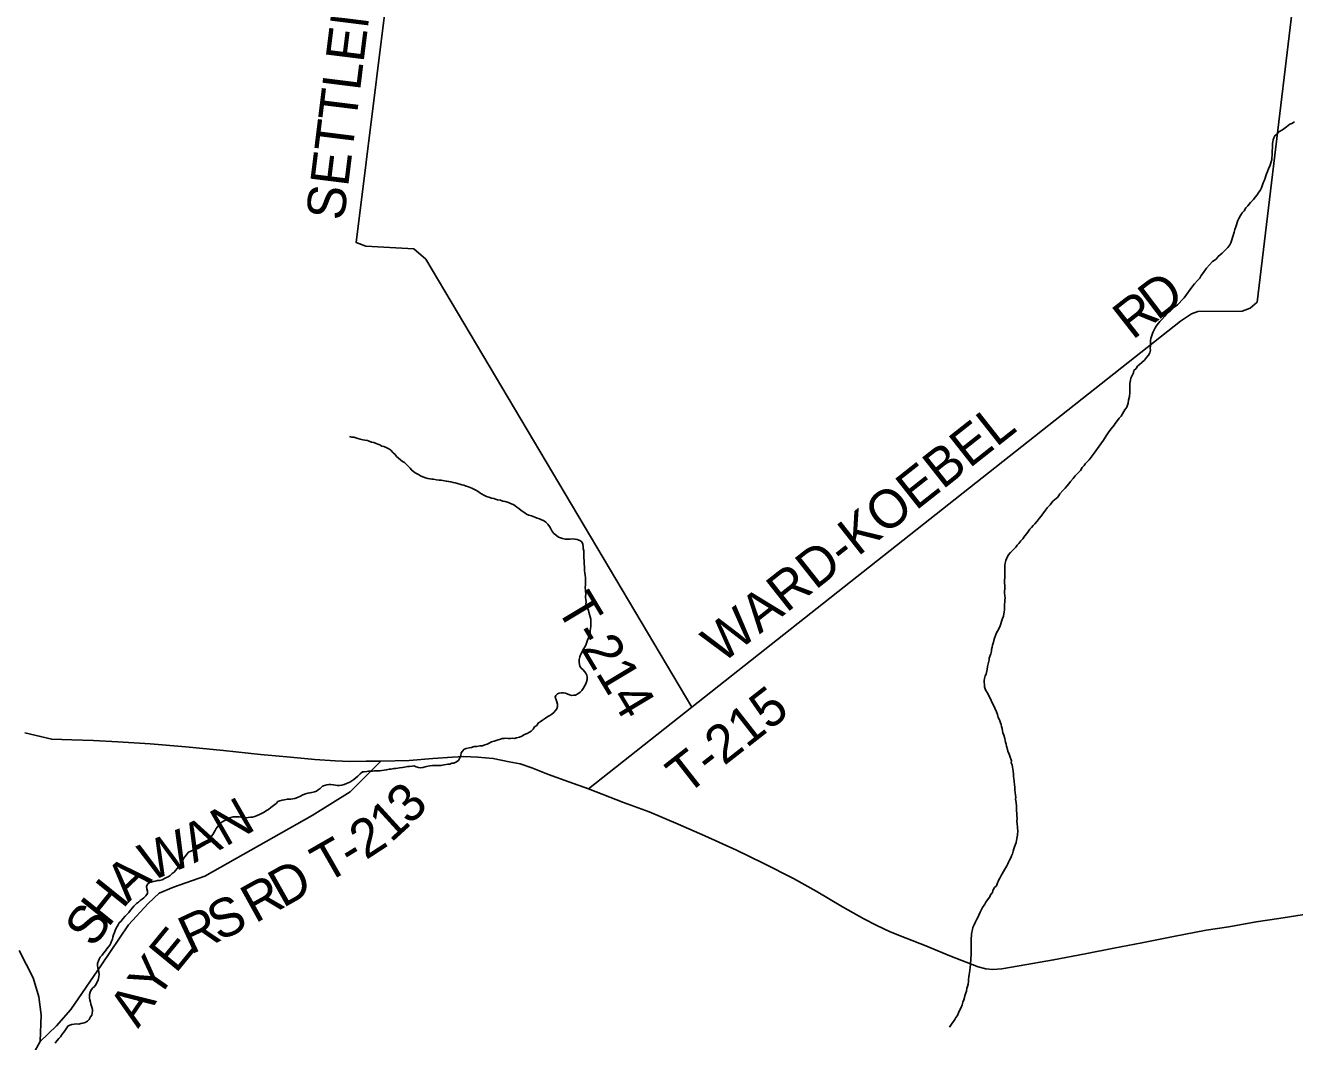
# Model space of a CAD drawing. Extents: x 0.4 to 34.4, y -2.1 to 19.9.
# Drawn here: x 5.213 to 7.097, y 12.684 to 14.193 of the extents above; entities that cross this region are included whole.
import ezdxf

# ---------------------------------------------------------------- set-up
doc = ezdxf.new("R2010")
doc.units = 0
for name, color, linetype in [('GM_X_County_Road', 7, 'Continuous'), ('GM_X_Minor_River', 7, 'Continuous'), ('GM_X_State_Route', 7, 'Continuous'), ('GM_X_Township_Road', 7, 'Continuous'), ('GM_X_Township_Road_Text', 7, 'Continuous')]:
    doc.layers.add(name, color=color, linetype=linetype)

msp = doc.modelspace()

# ---------------------------------------------------------------- linework, layer by layer
at = {"layer": 'GM_X_County_Road'}
msp.add_lwpolyline([(5.2037, 12.819), (5.2246, 12.7784), (5.233, 12.7503), (5.2363, 12.7235), (5.2347, 12.6842), (5.1932, 12.6088)], dxfattribs=at)
at = {"layer": 'GM_X_Minor_River'}
for points in [[(7.0789, 14.0375), (7.0735, 14.0345), (7.0707, 14.0312), (7.0676, 14.0289), (7.066, 14.0255), (7.0652, 14.0225), (7.0647, 14.0199), (7.0643, 14.0172), (7.0642, 14.0138), (7.0642, 14.0107), (7.0637, 14.0069), (7.0636, 14.0035), (7.0635, 13.9993), (7.0631, 13.9963), (7.063, 13.9933), (7.0618, 13.9887), (7.0605, 13.9849), (7.0581, 13.9796), (7.0565, 13.9755), (7.0553, 13.9725), (7.0544, 13.9691), (7.0532, 13.966), (7.0516, 13.9619), (7.0504, 13.9589), (7.0492, 13.9558), (7.0476, 13.9517), (7.0456, 13.9475), (7.044, 13.9449), (7.0416, 13.9411), (7.0385, 13.9374), (7.0357, 13.9344), (7.0315, 13.9299), (7.0275, 13.925), (7.0248, 13.9217), (7.022, 13.9172), (7.0193, 13.9142), (7.0165, 13.9104), (7.0141, 13.9059), (7.0129, 13.9032), (7.0117, 13.9002), (7.0105, 13.8964), (7.0097, 13.8934), (7.0084, 13.8896), (7.0072, 13.8855), (7.0056, 13.8805), (7.0047, 13.8779), (7.0039, 13.8745), (7.0023, 13.8696), (7.0007, 13.8669), (6.9979, 13.8628), (6.994, 13.8591), (6.9893, 13.8546), (6.9835, 13.8494), (6.9804, 13.8456), (6.9753, 13.8419), (6.9706, 13.8371), (6.9663, 13.8322), (6.9628, 13.8273), (6.9601, 13.8239), (6.9581, 13.8213), (6.9561, 13.8175), (6.9526, 13.8138), (6.9483, 13.8089), (6.9459, 13.8059), (6.942, 13.8007), (6.9393, 13.7973), (6.9357, 13.7917), (6.9329, 13.7883), (6.9298, 13.7845), (6.9255, 13.7804), (6.9232, 13.7778), (6.9181, 13.7741), (6.9123, 13.7685), (6.908, 13.7652), (6.9041, 13.761), (6.8998, 13.7558), (6.8971, 13.7532), (6.8951, 13.7505), (6.8916, 13.746), (6.89, 13.7434), (6.8884, 13.7408), (6.8872, 13.7378), (6.886, 13.7351), (6.8844, 13.7306), (6.8835, 13.7279), (6.8831, 13.7249), (6.883, 13.7211), (6.8829, 13.7169), (6.8825, 13.7131), (6.8828, 13.7104), (6.8819, 13.7067), (6.8803, 13.7033), (6.8772, 13.6995), (6.8741, 13.6958), (6.8702, 13.692), (6.8667, 13.6891), (6.8639, 13.6868), (6.8616, 13.6834), (6.8585, 13.6801), (6.858, 13.677), (6.8556, 13.6729)], [(7.097, 14.0493), (7.0928, 14.0471), (7.0901, 14.046), (7.0847, 14.0419), (7.0789, 14.0375)], [(6.8556, 13.6729), (6.854, 13.6691), (6.8532, 13.6661), (6.8523, 13.6608), (6.8522, 13.6555), (6.8525, 13.652), (6.8524, 13.6475), (6.8519, 13.6418), (6.8506, 13.6361), (6.8497, 13.6319), (6.8477, 13.6259), (6.8449, 13.6221), (6.8434, 13.6195), (6.8414, 13.6161), (6.8394, 13.6127), (6.8363, 13.6093), (6.8339, 13.6063), (6.8308, 13.6018), (6.8292, 13.5992), (6.8245, 13.5939), (6.8213, 13.5891), (6.8174, 13.5834), (6.8134, 13.577), (6.8095, 13.5714), (6.8044, 13.5643), (6.7993, 13.5575), (6.7949, 13.5515), (6.7918, 13.5478), (6.7863, 13.5418), (6.7844, 13.5391), (6.7816, 13.5365), (6.7789, 13.5316), (6.775, 13.5279), (6.7714, 13.5238), (6.7683, 13.52), (6.7644, 13.5155), (6.762, 13.5122), (6.7589, 13.5088), (6.7562, 13.5054), (6.753, 13.5021), (6.7483, 13.4972), (6.7456, 13.4923), (6.7382, 13.4863), (6.7339, 13.4811), (6.7296, 13.4762), (6.726, 13.4717), (6.7229, 13.4668), (6.7205, 13.4642), (6.7178, 13.4608), (6.7146, 13.4567), (6.7111, 13.4526), (6.7088, 13.45), (6.7064, 13.4474), (6.7041, 13.4447), (6.7021, 13.4417), (6.6994, 13.4384), (6.6966, 13.4346), (6.6935, 13.4305), (6.6907, 13.4275), (6.6876, 13.4237), (6.6852, 13.4211), (6.6829, 13.4181), (6.6782, 13.4133), (6.6751, 13.4099), (6.6719, 13.4061), (6.6695, 13.4009), (6.6683, 13.3982), (6.6671, 13.3941), (6.667, 13.3914), (6.6669, 13.3868), (6.6668, 13.3826), (6.6667, 13.3781), (6.6666, 13.3735), (6.6665, 13.3682), (6.6664, 13.3655), (6.6667, 13.3602), (6.6666, 13.356), (6.6665, 13.3526), (6.6665, 13.3492), (6.6668, 13.3461), (6.6671, 13.3423), (6.667, 13.3397), (6.6669, 13.3366), (6.6665, 13.3336), (6.6664, 13.329), (6.6663, 13.3256), (6.6658, 13.3214), (6.6654, 13.3188), (6.6646, 13.3157), (6.6633, 13.3119), (6.6621, 13.3078), (6.6609, 13.304), (6.6597, 13.301), (6.658, 13.2968), (6.656, 13.2931), (6.6541, 13.2897), (6.6529, 13.287), (6.6516, 13.2829), (6.6504, 13.2795), (6.65, 13.2768), (6.6483, 13.2723)], [(5.8162, 13.5189), (5.8135, 13.5193), (5.8105, 13.5201), (5.8067, 13.5209), (5.8029, 13.5225), (5.7995, 13.5237), (5.7965, 13.5261), (5.7927, 13.5277), (5.7901, 13.5296), (5.786, 13.5327), (5.7838, 13.5354), (5.7812, 13.5385), (5.7782, 13.5412), (5.7756, 13.5436), (5.7725, 13.5451), (5.7695, 13.5475), (5.7666, 13.5502), (5.7639, 13.5525), (5.7617, 13.5556), (5.7587, 13.5583), (5.7554, 13.5618), (5.7524, 13.5642), (5.7482, 13.5658), (5.7452, 13.5673), (5.7422, 13.5681), (5.7392, 13.5697), (5.7361, 13.5709), (5.7335, 13.5721), (5.7301, 13.5733), (5.7267, 13.5741), (5.7233, 13.5753), (5.7206, 13.5762), (5.7168, 13.577), (5.7138, 13.5774), (5.71, 13.5782), (5.7066, 13.5795), (5.7032, 13.5803), (5.7005, 13.5811), (5.6975, 13.5815), (5.6941, 13.5823)], [(6.0521, 13.311), (6.0514, 13.3144), (6.0504, 13.3182), (6.0493, 13.3213), (6.0486, 13.324), (6.0475, 13.3274), (6.0464, 13.3305), (6.045, 13.3336), (6.0451, 13.337), (6.0448, 13.3404), (6.0444, 13.3431), (6.0446, 13.3496), (6.0443, 13.3522), (6.0443, 13.3549), (6.044, 13.3579), (6.0441, 13.3614), (6.0442, 13.3655), (6.0443, 13.369), (6.0443, 13.3724), (6.044, 13.3766), (6.0434, 13.38), (6.043, 13.3831), (6.0427, 13.3861), (6.0428, 13.3895), (6.0425, 13.3926), (6.0422, 13.396), (6.0423, 13.3987), (6.0419, 13.4013), (6.042, 13.4044), (6.0417, 13.4093), (6.0418, 13.4128), (6.0411, 13.4162), (6.0408, 13.4189), (6.0405, 13.4223), (6.0387, 13.4258), (6.0357, 13.4277), (6.0319, 13.4293), (6.0285, 13.4301), (6.0247, 13.4302), (6.0216, 13.4299), (6.0182, 13.4299), (6.014, 13.43), (6.0102, 13.4308), (6.0072, 13.4317), (6.0041, 13.4329), (6.0011, 13.4352), (5.9974, 13.4383), (5.9944, 13.4425), (5.9922, 13.446), (5.9908, 13.4487), (5.9882, 13.4522), (5.9852, 13.4553), (5.9822, 13.4576), (5.9792, 13.4588), (5.9758, 13.46), (5.9727, 13.4612), (5.969, 13.4624), (5.964, 13.4644), (5.9603, 13.4656), (5.9569, 13.4672), (5.9542, 13.4688), (5.9516, 13.4707), (5.9482, 13.4731), (5.9456, 13.4754), (5.9422, 13.4774), (5.9396, 13.4797), (5.937, 13.4813), (5.9332, 13.4829), (5.9298, 13.4841), (5.9252, 13.4857), (5.9215, 13.4865), (5.918, 13.4877), (5.9135, 13.4885), (5.9108, 13.4893), (5.9082, 13.4902), (5.9048, 13.491), (5.9006, 13.4922), (5.8972, 13.493), (5.8934, 13.495), (5.89, 13.4973), (5.8874, 13.4989), (5.8848, 13.5005), (5.8814, 13.5024), (5.8757, 13.5056), (5.8731, 13.5068), (5.8705, 13.5076), (5.8674, 13.5088), (5.8636, 13.51), (5.8606, 13.5108), (5.8576, 13.5116), (5.8545, 13.5124), (5.8508, 13.5133), (5.8477, 13.5141), (5.8443, 13.5149), (5.8413, 13.5154), (5.8375, 13.5162), (5.8299, 13.5175), (5.8272, 13.5175), (5.823, 13.518), (5.8188, 13.5188), (5.8162, 13.5189)], [(5.8459, 13.0971), (5.849, 13.0975), (5.8517, 13.0986), (5.8556, 13.1015), (5.858, 13.1053), (5.8592, 13.1087), (5.8596, 13.1125), (5.8616, 13.1151), (5.8643, 13.1181), (5.867, 13.1192), (5.8716, 13.1199), (5.8751, 13.1206), (5.8789, 13.122), (5.8831, 13.1223), (5.8873, 13.123), (5.8912, 13.1233), (5.895, 13.1244), (5.8984, 13.1255), (5.9015, 13.1269), (5.9046, 13.1292), (5.9088, 13.1302), (5.9146, 13.132), (5.9181, 13.1331), (5.9208, 13.1338), (5.9234, 13.1342), (5.9261, 13.1345), (5.9295, 13.134), (5.933, 13.134), (5.9364, 13.1343), (5.9391, 13.1342), (5.9417, 13.135), (5.9463, 13.136), (5.9498, 13.1375), (5.9537, 13.1397), (5.9579, 13.1415), (5.961, 13.1434), (5.9637, 13.1448), (5.9664, 13.1478), (5.9688, 13.1512), (5.9719, 13.1534), (5.9739, 13.1568), (5.977, 13.1587), (5.9805, 13.1613), (5.9847, 13.1642), (5.9886, 13.1664), (5.9913, 13.1679), (5.9944, 13.1701), (5.9971, 13.1724), (5.9999, 13.1754), (6.0018, 13.178), (6.003, 13.1814), (6.0027, 13.1848), (6.0017, 13.1883), (6.0006, 13.1913), (5.9995, 13.1952), (6.0004, 13.1978), (6.0027, 13.2004), (6.0054, 13.2015), (6.0088, 13.2018), (6.0115, 13.2018), (6.0145, 13.2013), (6.0172, 13.2002), (6.0206, 13.199), (6.024, 13.1977), (6.0271, 13.1981), (6.0297, 13.1984), (6.0328, 13.2002), (6.0363, 13.2028), (6.039, 13.2051), (6.041, 13.2081), (6.043, 13.2115), (6.0446, 13.2153), (6.0458, 13.2183), (6.0467, 13.2217), (6.0467, 13.2251), (6.0464, 13.2282), (6.045, 13.2312), (6.0409, 13.2359), (6.0379, 13.2386), (6.036, 13.2413), (6.0353, 13.244), (6.035, 13.2474), (6.0351, 13.2512), (6.036, 13.255), (6.0368, 13.258), (6.0384, 13.2606), (6.04, 13.264), (6.0416, 13.2678), (6.0436, 13.2704), (6.0455, 13.2742), (6.0464, 13.2772), (6.0472, 13.2799), (6.0492, 13.2844), (6.0504, 13.2886), (6.0513, 13.2912), (6.0513, 13.2943), (6.0518, 13.2969), (6.0522, 13.3007), (6.0523, 13.3045), (6.0524, 13.3076), (6.0521, 13.311)], [(6.6483, 13.2723), (6.6479, 13.2696), (6.6471, 13.2662), (6.647, 13.2635), (6.6458, 13.2598), (6.6437, 13.2533), (6.6437, 13.2507), (6.6424, 13.2469), (6.6411, 13.2408), (6.6407, 13.2363), (6.6398, 13.2321), (6.639, 13.2295), (6.6378, 13.2268), (6.6366, 13.223), (6.6361, 13.22), (6.636, 13.2173), (6.6364, 13.2143), (6.6366, 13.2105), (6.6377, 13.2078), (6.6384, 13.2051), (6.6414, 13.2009), (6.6436, 13.1963), (6.6454, 13.1928), (6.6479, 13.1867), (6.6501, 13.1832), (6.652, 13.179), (6.6545, 13.1736), (6.6559, 13.1694), (6.657, 13.1652), (6.6588, 13.1618), (6.6602, 13.1572), (6.6613, 13.1545), (6.662, 13.1518), (6.6627, 13.1487), (6.6634, 13.1453), (6.6637, 13.1426), (6.6652, 13.1388), (6.6666, 13.1342), (6.6673, 13.1312), (6.668, 13.1285), (6.6687, 13.1254), (6.6694, 13.1228), (6.6708, 13.1178), (6.6715, 13.1151), (6.6733, 13.1109), (6.6744, 13.1078), (6.6765, 13.1006), (6.6764, 13.0979), (6.6775, 13.0948), (6.6782, 13.0914), (6.6792, 13.0853), (6.6795, 13.0811), (6.6798, 13.0777), (6.6801, 13.0746), (6.6808, 13.0708), (6.681, 13.0647), (6.6817, 13.062), (6.6816, 13.0579), (6.6826, 13.0498), (6.6829, 13.0464), (6.6828, 13.0438), (6.6835, 13.0388), (6.6841, 13.0335), (6.6843, 13.0262), (6.6847, 13.0236), (6.6846, 13.019), (6.6849, 13.0156), (6.6848, 13.011), (6.6851, 13.0068), (6.6857, 13.003), (6.6857, 13.0003), (6.686, 12.9973), (6.6854, 12.9904), (6.685, 12.9878), (6.6841, 12.9825), (6.6837, 12.9798), (6.6812, 12.973), (6.6804, 12.97), (6.6792, 12.9666), (6.678, 12.9628), (6.6768, 12.9598), (6.6755, 12.9568), (6.6739, 12.9534), (6.6723, 12.9504), (6.6711, 12.9477), (6.6696, 12.9451), (6.6684, 12.9424), (6.6668, 12.9398), (6.6648, 12.9364), (6.6628, 12.933), (6.6608, 12.9296), (6.6596, 12.9266), (6.658, 12.924), (6.6552, 12.918), (6.6544, 12.9153), (6.6517, 12.9127), (6.6489, 12.9082), (6.6485, 12.9055), (6.6457, 12.9018), (6.6445, 12.8987), (6.6413, 12.8946)], [(5.5151, 13.0157), (5.5177, 13.0168), (5.5212, 13.0175), (5.5243, 13.0178), (5.5273, 13.0178), (5.5303, 13.0177), (5.5334, 13.0173), (5.5364, 13.0168), (5.5402, 13.0164), (5.5437, 13.0167), (5.5471, 13.017), (5.5498, 13.017), (5.5536, 13.018), (5.5571, 13.0195), (5.5606, 13.0213), (5.5644, 13.0232), (5.5671, 13.0246), (5.5706, 13.0269), (5.5737, 13.0287), (5.5772, 13.0313), (5.5811, 13.0347), (5.5849, 13.0376), (5.5877, 13.0402), (5.5904, 13.0413), (5.5938, 13.0424), (5.5973, 13.0431), (5.6015, 13.0438), (5.6068, 13.0441), (5.6099, 13.0444), (5.6129, 13.0447), (5.6168, 13.0462), (5.621, 13.0484), (5.6249, 13.0502), (5.6287, 13.0517), (5.6322, 13.0527), (5.6352, 13.0531), (5.6379, 13.0538), (5.6418, 13.0548), (5.6448, 13.0559), (5.6475, 13.0578), (5.6506, 13.0596), (5.6538, 13.063), (5.6568, 13.0641), (5.6603, 13.0652), (5.6634, 13.0659), (5.6664, 13.0658), (5.6698, 13.0654), (5.6733, 13.0645), (5.6759, 13.0641), (5.6793, 13.0644), (5.6828, 13.0648), (5.6862, 13.0658), (5.6893, 13.0673), (5.692, 13.068), (5.6947, 13.0691), (5.6974, 13.071), (5.7005, 13.0732), (5.7032, 13.0754), (5.7063, 13.078), (5.7099, 13.0814), (5.7134, 13.0844), (5.716, 13.0847), (5.7195, 13.085), (5.7221, 13.0853), (5.7248, 13.0857), (5.7279, 13.0856), (5.7305, 13.0859), (5.7359, 13.0858), (5.7389, 13.0862), (5.742, 13.0865), (5.7454, 13.0868), (5.7489, 13.0875), (5.7527, 13.0882), (5.7558, 13.0885), (5.7596, 13.0892), (5.7627, 13.0895), (5.7657, 13.0899), (5.7684, 13.0906), (5.7726, 13.0909), (5.7757, 13.0916), (5.7799, 13.0923), (5.7829, 13.0926), (5.7868, 13.0929), (5.7894, 13.0932), (5.7928, 13.092), (5.7962, 13.0908), (5.7989, 13.0904), (5.8027, 13.0907), (5.8062, 13.0918), (5.8104, 13.0929), (5.8135, 13.0936), (5.8173, 13.0939), (5.8203, 13.0938), (5.8238, 13.0941), (5.8264, 13.0941), (5.8302, 13.094), (5.8341, 13.0947), (5.8375, 13.0954), (5.8402, 13.0957), (5.8429, 13.0961), (5.8459, 13.0971)], [(5.3081, 12.7486), (5.3081, 12.7513), (5.3082, 12.7539), (5.309, 12.7573), (5.3102, 12.76), (5.3126, 12.7634), (5.3153, 12.766), (5.3177, 12.769), (5.3189, 12.7716), (5.3209, 12.775), (5.3213, 12.7777), (5.3218, 12.7807), (5.3222, 12.7834), (5.3219, 12.7872), (5.3212, 12.7906), (5.3205, 12.7937), (5.3198, 12.7967), (5.3199, 12.8001), (5.3215, 12.8039), (5.3224, 12.8066), (5.3239, 12.8092), (5.3267, 12.8122), (5.329, 12.8152), (5.3318, 12.8186), (5.3337, 12.8216), (5.3357, 12.8242), (5.3381, 12.8272), (5.3397, 12.8302), (5.3409, 12.8332), (5.3421, 12.8359), (5.3429, 12.8389), (5.3438, 12.8423), (5.345, 12.8461), (5.3462, 12.8487), (5.3478, 12.8525), (5.3506, 12.8574), (5.3522, 12.8604), (5.3549, 12.863), (5.3573, 12.8664), (5.3608, 12.8701), (5.3635, 12.8728), (5.3662, 12.8758), (5.369, 12.8791), (5.3713, 12.8821), (5.3737, 12.8851), (5.378, 12.8889), (5.3807, 12.8911), (5.3834, 12.8933), (5.3861, 12.8956), (5.3888, 12.8974), (5.3916, 12.9004), (5.3939, 12.9038), (5.394, 12.9072), (5.3933, 12.9106), (5.3927, 12.9141), (5.3939, 12.9175), (5.397, 12.9201), (5.3997, 12.9208), (5.4027, 12.9215), (5.4054, 12.9222), (5.4089, 12.9229), (5.4119, 12.9232), (5.4158, 12.9243), (5.4196, 12.9261), (5.4223, 12.9276), (5.425, 12.9287), (5.4277, 12.9306), (5.4308, 12.9335), (5.4336, 12.9354), (5.4359, 12.938), (5.4383, 12.941), (5.441, 12.9448), (5.4434, 12.9478), (5.4457, 12.9512), (5.4477, 12.9557), (5.4501, 12.9587), (5.4525, 12.9621), (5.4552, 12.9651), (5.4583, 12.9669), (5.4617, 12.968), (5.4652, 12.9691), (5.4679, 12.9701), (5.471, 12.9716), (5.4748, 12.9742), (5.4779, 12.9757), (5.4806, 12.9775), (5.4837, 12.9801), (5.4861, 12.9831), (5.4881, 12.9861), (5.4893, 12.9888), (5.4912, 12.9914), (5.4932, 12.9948), (5.4948, 12.9974), (5.496, 13.0001), (5.498, 13.0027), (5.5003, 13.0057), (5.5031, 13.0087), (5.5062, 13.0109), (5.5089, 13.0124), (5.5123, 13.0142), (5.5151, 13.0157)], [(6.6413, 12.8946), (6.6386, 12.8909), (6.637, 12.8879), (6.6339, 12.8833), (6.6315, 12.8792), (6.6303, 12.8762), (6.6282, 12.8717), (6.6266, 12.8683), (6.6251, 12.8656), (6.6235, 12.8618), (6.6211, 12.8573), (6.6194, 12.8532), (6.6186, 12.8505), (6.6178, 12.8464), (6.6173, 12.8437), (6.6173, 12.8407), (6.6168, 12.838), (6.6167, 12.8334), (6.6166, 12.8289), (6.6169, 12.8254), (6.6168, 12.822), (6.6168, 12.8186), (6.6166, 12.8118), (6.6165, 12.8083), (6.6164, 12.8042), (6.616, 12.8011), (6.6159, 12.7981), (6.6155, 12.7947), (6.615, 12.7897), (6.6145, 12.7867), (6.6141, 12.7837), (6.6136, 12.7802), (6.6131, 12.7764), (6.6127, 12.773), (6.6122, 12.7692), (6.6114, 12.7658), (6.6106, 12.7632), (6.6101, 12.759), (6.6089, 12.7564), (6.6076, 12.7518), (6.6068, 12.7492), (6.606, 12.7458), (6.6047, 12.7424), (6.6035, 12.7386), (6.6019, 12.7348), (6.5995, 12.7303), (6.5979, 12.7265), (6.5963, 12.7227), (6.5943, 12.7197), (6.5927, 12.7167), (6.5908, 12.7137), (6.5888, 12.7111), (6.5868, 12.7084), (6.5845, 12.7054)], [(5.257, 12.6818), (5.2594, 12.6852), (5.2625, 12.6886), (5.2648, 12.6912), (5.2676, 12.6949), (5.27, 12.6979), (5.2723, 12.7013), (5.2743, 12.7043), (5.2759, 12.707), (5.279, 12.7084), (5.2816, 12.7092), (5.2855, 12.7098), (5.2885, 12.7102), (5.292, 12.7101), (5.295, 12.7108), (5.2981, 12.7111), (5.3015, 12.7122), (5.305, 12.7144), (5.3074, 12.717), (5.3097, 12.7208), (5.3113, 12.7234), (5.3121, 12.7261), (5.3126, 12.7291), (5.3123, 12.7318), (5.3116, 12.7349), (5.3102, 12.7394), (5.3095, 12.7425), (5.3084, 12.7459), (5.3081, 12.7486)]]:
    msp.add_lwpolyline(points, dxfattribs=at)
at = {"layer": 'GM_X_State_Route'}
msp.add_lwpolyline([(5.2119, 13.1424), (5.2521, 13.1328), (5.282, 13.1318), (5.3138, 13.1311), (5.3502, 13.1288), (5.3979, 13.1261), (5.4508, 13.1214), (5.5068, 13.1163), (5.5621, 13.1104), (5.6063, 13.1062), (5.6427, 13.1028), (5.6729, 13.101), (5.6945, 13.1), (5.7188, 13.1001), (5.7405, 13.1002), (5.7828, 13.1014), (5.8177, 13.1041), (5.8468, 13.106), (5.8635, 13.107), (5.8847, 13.106), (5.9074, 13.1043), (5.9312, 13.0995), (5.9471, 13.0963), (5.9645, 13.0904), (5.9894, 13.0807), (6.0196, 13.0698), (6.0486, 13.0593), (6.1007, 13.0391), (6.1388, 13.025), (6.1818, 13.0068), (6.2214, 12.9894), (6.2685, 12.9681), (6.3081, 12.9487), (6.3529, 12.9259), (6.3865, 12.9074), (6.426, 12.8839), (6.4576, 12.8661), (6.4769, 12.8565), (6.4968, 12.8468), (6.5202, 12.8375), (6.5493, 12.8262), (6.5851, 12.8114), (6.627, 12.7951), (6.6387, 12.7919), (6.6489, 12.7911), (6.6626, 12.7921), (6.688, 12.7964), (6.7392, 12.8053), (6.7859, 12.8143), (6.8284, 12.8226), (6.8701, 12.8305), (6.9171, 12.8399), (6.9657, 12.8493), (6.9991, 12.8546), (7.0397, 12.8618), (7.0734, 12.8667), (7.1144, 12.8731)], dxfattribs=at)
at = {"layer": 'GM_X_Township_Road'}
for points in [[(6.0486, 13.0593), (6.2023, 13.1806), (6.9275, 13.7533), (6.9437, 13.7644), (6.9532, 13.768), (7.0189, 13.7683), (7.0311, 13.7726), (7.0415, 13.7819), (7.1029, 14.2928), (7.1535, 14.6887)], [(6.2023, 13.1806), (5.8073, 13.8455), (5.7894, 13.8608), (5.7182, 13.8651), (5.7038, 13.8704), (5.7946, 14.5981)], [(5.2347, 12.6842), (5.2589, 12.7074), (5.2801, 12.7314), (5.326, 12.7977), (5.3658, 12.8572), (5.395, 12.8891), (5.4115, 12.9041), (5.4329, 12.9133), (5.479, 12.9294), (5.6387, 13.0197), (5.6949, 13.0547), (5.7405, 13.1002)]]:
    msp.add_lwpolyline(points, dxfattribs=at)

# ---------------------------------------------------------------- texts
at = {"layer": 'GM_X_Township_Road_Text'}
for s, height, rotation, p in [('SETTLEMYRE', 0.05682, 82.9015, (5.6855, 13.9016)), ('D', 0.0568, 37.1475, (6.893, 13.7534)), ('R', 0.0568, 38.0947, (6.8564, 13.7247)), ('WARD-KOEBEL', 0.056818, 38.2942, (6.2464, 13.2438)), ('T-214', 0.05682, 300.9632, (5.9998, 13.3289)), ('T-215', 0.05682, 38.047, (6.1935, 13.0486)), ('3', 0.0568, 45.1805, (5.7835, 13.004)), ('N', 0.0568, 29.6975, (5.5095, 12.9726)), ('1', 0.0568, 42.4489, (5.7555, 12.9783)), ('W', 0.0568, 22.4102, (5.3973, 12.9209)), ('A', 0.0568, 27.5614, (5.4632, 12.9483)), ('2', 0.0568, 33.1902, (5.7183, 12.953)), ('T', 0.0568, 29.8326, (5.6585, 12.9178)), ('-', 0.0568, 31.4956, (5.6969, 12.9398)), ('A', 0.0568, 43.3022, (5.3655, 12.8895)), ('D', 0.0568, 29.4272, (5.5951, 12.8817)), ('H', 0.0568, 51.1809, (5.3355, 12.8521)), ('R', 0.0568, 29.0103, (5.5539, 12.8589)), ('S', 0.0568, 25.2245, (5.5002, 12.8324)), ('S', 0.0568, 55.2345, (5.3143, 12.8215)), ('R', 0.0568, 24.9992, (5.4577, 12.8125)), ('E', 0.0568, 50.6367, (5.436, 12.7838)), ('Y', 0.0568, 55.2652, (5.4082, 12.7436)), ('A', 0.0568, 55.7371, (5.3802, 12.7024))]:
    msp.add_text(s, height=height, rotation=rotation, dxfattribs=at).set_placement(p)

doc.saveas('drawing.dxf')
